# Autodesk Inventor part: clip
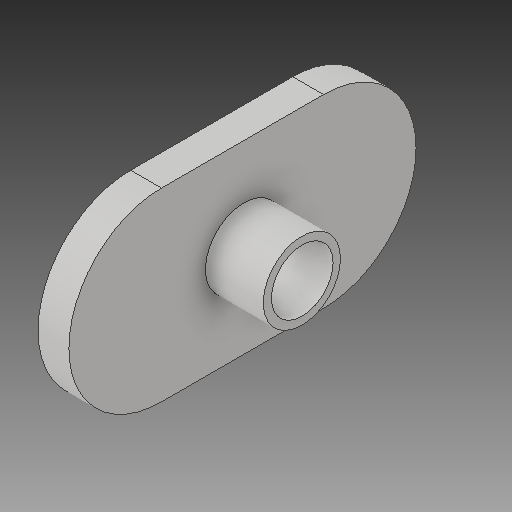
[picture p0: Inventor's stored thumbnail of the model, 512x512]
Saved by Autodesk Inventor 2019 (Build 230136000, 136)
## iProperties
Created: 2020-02
Part Number: clip
Material: Generic
Document SubType Name: Modeling
Designer: ash
Density: 1 g/cm^3
Appearance: Default
Author: ash
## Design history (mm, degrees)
sketch "Sketch1"
  geometry: L1 (0, 4.266)-(0, -18.234); L2 (-6, -1.734)-(-6, -12.234); L3 (6, -12.234)-(6, -1.734); A1 r 6 centre (0, -1.734) between (6, -1.734) and (-6, -1.734); A2 r 6 centre (0, -12.234) between (-6, -12.234) and (6, -12.234); 3 further points
  constraints: 8 end point, 6 point on circle, 4 tangent, 2 centre point, 2 point on line, 1 coincident, 1 midpoint, 1 parallel, 1 vertical
  dimensions: "d0" = 12 distance between parallel lines of L2 L3; "d1" = 22.5 distance of L1.end L1.start
sketch "Sketch2"
  geometry: C1 r 2 at (0, -7.105); 1 further point
  constraints: 1 centre point
  dimensions: "d2" = 4 diameter of C1
extrude "Extrusion2" join sketch "Sketch1" distance "d5" = 2; taper "d6" = 0 deg
sketch "Sketch3"
  geometry: L1 (8.965, 1.642)-(8.549, 1.175); L2 (8.549, 1.175)-(9.287, 1.175); A1 r 2.5 centre (7.08, 0) between (8.965, 1.642) and (9.287, 1.175); 1 further point
  constraints: 4 end point, 2 point on circle, 1 centre point, 1 horizontal
  dimensions: "d8" = 5 diameter of A1; "d13" = 0.4676 vertical distance of L1.start L1.end
extrude "Extrusion3" join sketch "Sketch3" distance "d9" = 3.75; taper "d10" = 0 deg
extrude "Extrusion4" cut sketch "Sketch2" distance "d11" = 3.75; taper "d12" = 0 deg
body "Solid1"
other parameters: "sa_0" = 4
